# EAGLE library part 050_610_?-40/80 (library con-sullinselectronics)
.050 DIP EDGE CARD CONNECTOR .050 [1.27mm] CONTACT CENTERS .610" INSULATEOR HEIGHT Source: .050 DIP EDGE CARD.pdf
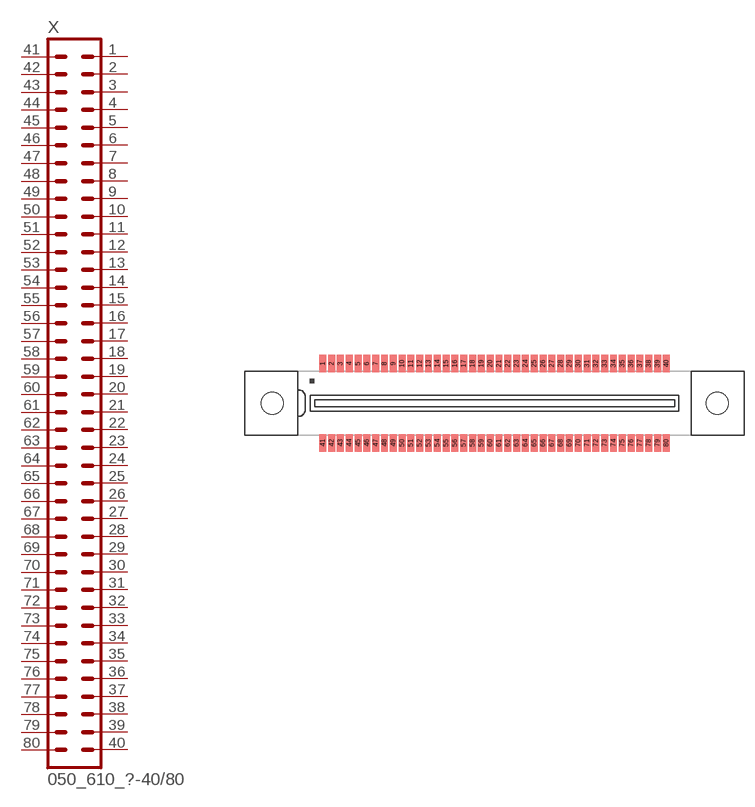
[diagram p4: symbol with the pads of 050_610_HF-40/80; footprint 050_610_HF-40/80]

Designator prefix X

## 050_610_HF-40/80 (OC_FARNELL: unknown; OC_NEWARK: unknown)  [050_610_HF-40/80]
1  1  pas
2  2  pas
3  3  pas
4  4  pas
5  5  pas
6  6  pas
7  7  pas
8  8  pas
9  9  pas
10  10  pas
11  11  pas
12  12  pas
13  13  pas
14  14  pas
15  15  pas
16  16  pas
17  17  pas
18  18  pas
19  19  pas
20  20  pas
21  21  pas
22  22  pas
23  23  pas
24  24  pas
25  25  pas
26  26  pas
27  27  pas
28  28  pas
29  29  pas
30  30  pas
31  31  pas
32  32  pas
33  33  pas
34  34  pas
35  35  pas
36  36  pas
37  37  pas
38  38  pas
39  39  pas
40  40  pas
41  41  pas
42  42  pas
43  43  pas
44  44  pas
45  45  pas
46  46  pas
47  47  pas
48  48  pas
49  49  pas
50  50  pas
51  51  pas
52  52  pas
53  53  pas
54  54  pas
55  55  pas
56  56  pas
57  57  pas
58  58  pas
59  59  pas
60  60  pas
61  61  pas
62  62  pas
63  63  pas
64  64  pas
65  65  pas
66  66  pas
67  67  pas
68  68  pas
69  69  pas
70  70  pas
71  71  pas
72  72  pas
73  73  pas
74  74  pas
75  75  pas
76  76  pas
77  77  pas
78  78  pas
79  79  pas
80  80  pas

## Footprint 050_610_HF-40/80 (pad centres in mm)
.050 DIP EDGE CARD CONNECTOR SURFACE MOUNT .050 [1.27mm] CONTACT CENTERS .610" INSULATEOR HEIGHT Source: .050 DIP EDGE CARD.pdf
smd 1 x 2.5: 1 -24.765,5.715; 2 -23.495,5.715; 3 -22.225,5.715; 4 -20.955,5.715; 5 -19.685,5.715; 6 -18.415,5.715; 7 -17.145,5.715; 8 -15.875,5.715; 9 -14.605,5.715; 10 -13.335,5.715; 11 -12.065,5.715; 12 -10.795,5.715; 13 -9.525,5.715; 14 -8.255,5.715; 15 -6.985,5.715; 16 -5.715,5.715; 17 -4.445,5.715; 18 -3.175,5.715; 19 -1.905,5.715; 20 -0.635,5.715; 21 0.635,5.715; 22 1.905,5.715; 23 3.175,5.715; 24 4.445,5.715; 25 5.715,5.715; 26 6.985,5.715; 27 8.255,5.715; 28 9.525,5.715; 29 10.795,5.715; 30 12.065,5.715; 31 13.335,5.715; 32 14.605,5.715; 33 15.875,5.715; 34 17.145,5.715; 35 18.415,5.715; 36 19.685,5.715; 37 20.955,5.715; 38 22.225,5.715; 39 23.495,5.715; 40 24.765,5.715; 41 -24.765,-5.715; 42 -23.495,-5.715; 43 -22.225,-5.715; 44 -20.955,-5.715; 45 -19.685,-5.715; 46 -18.415,-5.715; 47 -17.145,-5.715; 48 -15.875,-5.715; 49 -14.605,-5.715; 50 -13.335,-5.715; 51 -12.065,-5.715; 52 -10.795,-5.715; 53 -9.525,-5.715; 54 -8.255,-5.715; 55 -6.985,-5.715; 56 -5.715,-5.715; 57 -4.445,-5.715; 58 -3.175,-5.715; 59 -1.905,-5.715; 60 -0.635,-5.715; 61 0.635,-5.715; 62 1.905,-5.715; 63 3.175,-5.715; 64 4.445,-5.715; 65 5.715,-5.715; 66 6.985,-5.715; 67 8.255,-5.715; 68 9.525,-5.715; 69 10.795,-5.715; 70 12.065,-5.715; 71 13.335,-5.715; 72 14.605,-5.715; 73 15.875,-5.715; 74 17.145,-5.715; 75 18.415,-5.715; 76 19.685,-5.715; 77 20.955,-5.715; 78 22.225,-5.715; 79 23.495,-5.715; 80 24.765,-5.715
hole 3.18 at -32.08,0
hole 3.18 at 32.08,0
